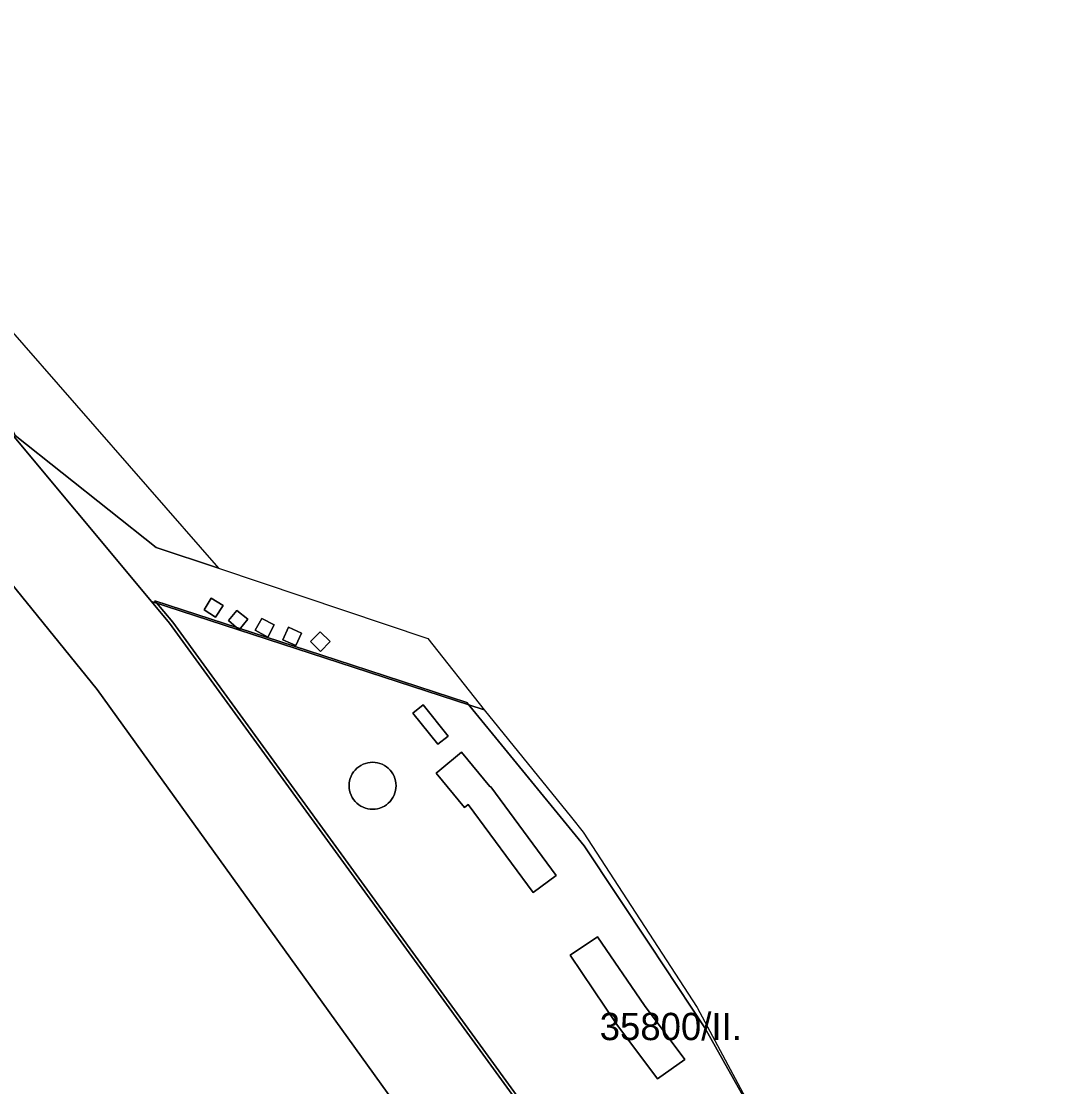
# Model space of a CAD drawing. Extents: x -535894 to -532834, y -1165802 to -1163645.
# Drawn here: x -533201.8 to -533014.4, y -1164702.6 to -1164507.5 of the extents above; entities that cross this region are included whole.
import ezdxf

# ---------------------------------------------------------------- set-up
doc = ezdxf.new("R2010")
doc.units = 0
for name, color, linetype in [('95620013', 7, 'Continuous'), ('95630013', 7, 'Continuous'), ('95640013', 7, 'Continuous'), ('95660013', 7, 'Continuous')]:
    doc.layers.add(name, color=color, linetype=linetype)

msp = doc.modelspace()

# ---------------------------------------------------------------- linework, layer by layer
at = {"layer": '95620013'}
msp.add_lwpolyline([(-533217.69, -1164548.05), (-533165.64, -1164607.65), (-533177.04, -1164603.82), (-533202.85, -1164583.35), (-533212.4, -1164563.33)], close=True, dxfattribs=at)
at = {"layer": '95630013'}
msp.add_lwpolyline([(-533218.62, -1164591.93), (-533187.88, -1164629.82), (-533107.67, -1164741.3)], dxfattribs=at)
at = {"layer": '95640013'}
for points in [[(-533286.31, -1164461.99), (-533266.97, -1164486.26), (-533227.22, -1164536.15), (-533217.69, -1164548.05), (-533212.4, -1164563.33), (-533202.85, -1164583.35), (-533177.04, -1164603.82), (-533165.64, -1164607.65), (-533127.31, -1164620.51), (-533116.98, -1164633.6), (-533177.92, -1164613.75), (-533205.86, -1164580.27), (-533235.68, -1164545.17), (-533280.62, -1164497.03), (-533292.65, -1164484.53)], [(-533116.98, -1164633.6), (-533101.02, -1164653.29), (-533098.87, -1164655.96), (-533077.99, -1164688.07), (-533051.48, -1164737.74), (-533049.69, -1164741.02), (-533051.79, -1164739.92), (-533060.24, -1164735.48), (-533067.33, -1164731.75), (-533074.43, -1164728.01), (-533080.87, -1164725.97), (-533088.71, -1164723.46), (-533096.72, -1164721.02), (-533100.33, -1164719.92), (-533174.61, -1164617.7), (-533177.92, -1164613.75)], [(-533166.97, -1164613.12), (-533164.82, -1164614.46), (-533166.17, -1164616.6), (-533168.3, -1164615.25)], [(-533166.97, -1164613.12), (-533168.3, -1164615.25), (-533166.17, -1164616.6), (-533164.82, -1164614.46)], [(-533162.26, -1164615.36), (-533160.26, -1164616.97), (-533161.84, -1164618.92), (-533163.84, -1164617.2)], [(-533162.26, -1164615.36), (-533163.84, -1164617.2), (-533161.84, -1164618.92), (-533160.26, -1164616.97)], [(-533157.74, -1164616.87), (-533158.93, -1164619), (-533156.63, -1164620.28), (-533155.47, -1164618.03)], [(-533157.74, -1164616.87), (-533155.47, -1164618.03), (-533156.63, -1164620.28), (-533158.93, -1164619)], [(-533152.85, -1164618.41), (-533150.43, -1164619.54), (-533151.48, -1164621.81), (-533153.89, -1164620.73)], [(-533152.85, -1164618.41), (-533153.89, -1164620.73), (-533151.48, -1164621.81), (-533150.43, -1164619.54)], [(-533147.06, -1164619.31), (-533148.81, -1164621.03), (-533146.98, -1164622.9), (-533145.23, -1164621.07)], [(-533147.06, -1164619.31), (-533145.23, -1164621.07), (-533146.98, -1164622.9), (-533148.81, -1164621.03)], [(-533128.16, -1164632.66), (-533123.6, -1164638.37), (-533125.49, -1164639.89), (-533130.05, -1164634.17)], [(-533123.6, -1164638.37), (-533128.16, -1164632.66), (-533130.05, -1164634.17), (-533125.49, -1164639.89)], [(-533121.17, -1164641.34), (-533115.99, -1164647.64), (-533115.76, -1164647.68), (-533103.81, -1164663.92), (-533108.03, -1164667.03), (-533119.95, -1164650.91), (-533120.62, -1164651.45), (-533125.8, -1164645.15), (-533125.15, -1164644.61)], [(-533115.76, -1164647.68), (-533115.99, -1164647.64), (-533121.17, -1164641.34), (-533125.15, -1164644.61), (-533125.8, -1164645.15), (-533120.62, -1164651.45), (-533119.95, -1164650.91), (-533108.03, -1164667.03), (-533103.81, -1164663.92)], [(-533136.981, -1164651.746), (-533137.43, -1164651.77), (-533137.88, -1164651.746), (-533138.324, -1164651.676), (-533138.759, -1164651.56), (-533139.179, -1164651.398), (-533139.58, -1164651.194), (-533139.957, -1164650.949), (-533140.307, -1164650.666), (-533140.626, -1164650.347), (-533140.909, -1164649.997), (-533141.154, -1164649.62), (-533141.358, -1164649.219), (-533141.519, -1164648.799), (-533141.636, -1164648.364), (-533141.706, -1164647.92), (-533141.73, -1164647.47), (-533141.706, -1164647.021), (-533141.636, -1164646.576), (-533141.519, -1164646.141), (-533141.358, -1164645.721), (-533141.154, -1164645.32), (-533140.909, -1164644.942), (-533140.626, -1164644.593), (-533140.307, -1164644.275), (-533139.957, -1164643.991), (-533139.58, -1164643.746), (-533139.179, -1164643.542), (-533138.759, -1164643.381), (-533138.324, -1164643.264), (-533137.88, -1164643.194), (-533137.43, -1164643.17), (-533136.981, -1164643.194), (-533136.536, -1164643.264), (-533136.101, -1164643.381), (-533135.681, -1164643.542), (-533135.28, -1164643.746), (-533134.903, -1164643.991), (-533134.553, -1164644.275), (-533134.234, -1164644.593), (-533133.951, -1164644.942), (-533133.706, -1164645.32), (-533133.502, -1164645.721), (-533133.341, -1164646.141), (-533133.224, -1164646.576), (-533133.154, -1164647.021), (-533133.13, -1164647.47), (-533133.154, -1164647.92), (-533133.224, -1164648.364), (-533133.341, -1164648.799), (-533133.502, -1164649.219), (-533133.706, -1164649.62), (-533133.951, -1164649.997), (-533134.234, -1164650.347), (-533134.553, -1164650.666), (-533134.903, -1164650.949), (-533135.28, -1164651.194), (-533135.681, -1164651.398), (-533136.101, -1164651.56), (-533136.536, -1164651.676)], [(-533136.981, -1164651.746), (-533136.536, -1164651.676), (-533136.101, -1164651.56), (-533135.681, -1164651.398), (-533135.28, -1164651.194), (-533134.903, -1164650.949), (-533134.553, -1164650.666), (-533134.234, -1164650.347), (-533133.951, -1164649.997), (-533133.706, -1164649.62), (-533133.502, -1164649.219), (-533133.341, -1164648.799), (-533133.224, -1164648.364), (-533133.154, -1164647.92), (-533133.13, -1164647.47), (-533133.154, -1164647.021), (-533133.224, -1164646.576), (-533133.341, -1164646.141), (-533133.502, -1164645.721), (-533133.706, -1164645.32), (-533133.951, -1164644.942), (-533134.234, -1164644.593), (-533134.553, -1164644.275), (-533134.903, -1164643.991), (-533135.28, -1164643.746), (-533135.681, -1164643.542), (-533136.101, -1164643.381), (-533136.536, -1164643.264), (-533136.981, -1164643.194), (-533137.43, -1164643.17), (-533137.88, -1164643.194), (-533138.324, -1164643.264), (-533138.759, -1164643.381), (-533139.179, -1164643.542), (-533139.58, -1164643.746), (-533139.957, -1164643.991), (-533140.307, -1164644.275), (-533140.626, -1164644.593), (-533140.909, -1164644.942), (-533141.154, -1164645.32), (-533141.358, -1164645.721), (-533141.519, -1164646.141), (-533141.636, -1164646.576), (-533141.706, -1164647.021), (-533141.73, -1164647.47), (-533141.706, -1164647.92), (-533141.636, -1164648.364), (-533141.519, -1164648.799), (-533141.358, -1164649.219), (-533141.154, -1164649.62), (-533140.909, -1164649.997), (-533140.626, -1164650.347), (-533140.307, -1164650.666), (-533139.957, -1164650.949), (-533139.58, -1164651.194), (-533139.179, -1164651.398), (-533138.759, -1164651.56), (-533138.324, -1164651.676), (-533137.88, -1164651.746), (-533137.43, -1164651.77)], [(-533096.25, -1164675.12), (-533087.66, -1164687.7), (-533080.27, -1164697.63), (-533085.28, -1164701.13), (-533092.73, -1164691.17), (-533101.27, -1164678.5)], [(-533080.27, -1164697.63), (-533087.66, -1164687.7), (-533096.25, -1164675.12), (-533101.27, -1164678.5), (-533092.73, -1164691.17), (-533085.28, -1164701.13)]]:
    msp.add_lwpolyline(points, close=True, dxfattribs=at)
for points in [[(-533205.86, -1164580.27), (-533177.92, -1164613.75), (-533174.61, -1164617.7), (-533100.33, -1164719.92)], [(-533107.67, -1164741.3), (-533187.88, -1164629.82), (-533218.62, -1164591.93)]]:
    msp.add_lwpolyline(points, dxfattribs=at)
at = {"layer": '95660013'}
msp.add_lwpolyline([(-533217.69, -1164548.05), (-533165.64, -1164607.65), (-533127.31, -1164620.51), (-533116.98, -1164633.6), (-533101.02, -1164653.29), (-533098.87, -1164655.96), (-533077.99, -1164688.07), (-533064.041, -1164714.206), (-533076.582, -1164691.833), (-533086.643, -1164676.675), (-533098.703, -1164658.507), (-533112.188, -1164642.002), (-533120.195, -1164632.203), (-533144.122, -1164624.407), (-533177.323, -1164613.591), (-533174.02, -1164617.541), (-533099.729, -1164719.761)], dxfattribs=at)
msp.add_lwpolyline([(-533064.041, -1164714.206), (-533051.48, -1164737.74), (-533049.69, -1164741.02), (-533048.53, -1164743.15), (-533047.398, -1164743.989), (-533028.041, -1164779.71), (-533014.38, -1164808.947), (-533037.332, -1164819.2), (-533075.566, -1164758.607), (-533078.437, -1164753.841), (-533082.42, -1164747.231), (-533086.574, -1164740.34), (-533089.802, -1164734.991), (-533093.522, -1164728.812), (-533097.748, -1164722.487), (-533099.729, -1164719.761), (-533174.02, -1164617.541), (-533177.323, -1164613.591), (-533144.122, -1164624.407), (-533120.195, -1164632.203), (-533112.188, -1164642.002), (-533098.703, -1164658.507), (-533086.643, -1164676.675), (-533076.582, -1164691.833)], close=True, dxfattribs=at)

# ---------------------------------------------------------------- texts
msp.add_text('35800/II.', height=5, rotation=0, dxfattribs=at).set_placement((-533095.852, -1164694.064))

doc.saveas('drawing.dxf')
